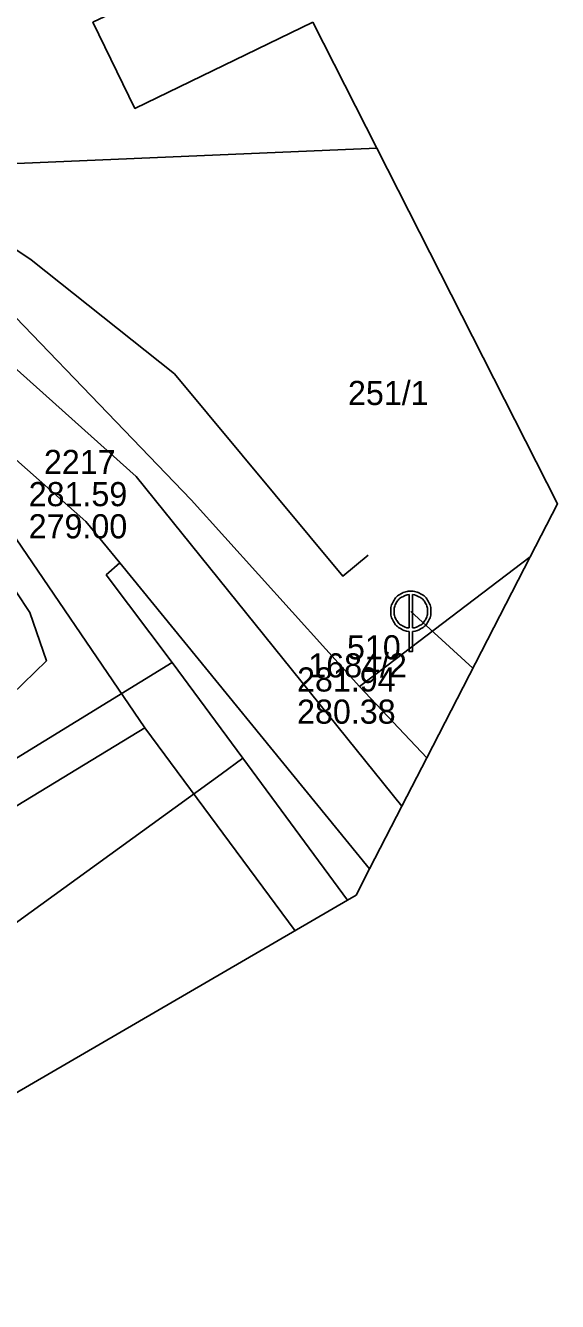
# Model space of a CAD drawing. Extents: x -571312 to -571060, y -1087128 to -1086933.
# Drawn here: x -571093.3 to -571060.1, y -1087060.8 to -1086981.5 of the extents above; entities that cross this region are included whole.
import ezdxf

# ---------------------------------------------------------------- set-up
doc = ezdxf.new("R2010")
doc.units = 0
for name, color, linetype in [('Default', 7, 'Continuous'), ('Elektro NN - vedení', 7, 'Continuous'), ('Kanalizační stoka', 7, 'Continuous'), ('Kanalizační šachta', 7, 'Continuous'), ('Parcela-polygon', 7, 'Continuous'), ('Parcela-text', 7, 'Continuous'), ('Popis šachty', 7, 'Continuous')]:
    doc.layers.add(name, color=color, linetype=linetype)

msp = doc.modelspace()

# ---------------------------------------------------------------- linework, layer by layer
at = {"layer": 'Default'}
for points in [[(-571069.383, -1087019.138), (-571069.641, -1087019.12), (-571069.903, -1087018.974), (-571070.2, -1087018.81), (-571070.365, -1087018.513), (-571070.53, -1087018.215), (-571070.53, -1087017.89), (-571070.53, -1087017.563), (-571070.362, -1087017.263), (-571070.193, -1087016.962), (-571069.895, -1087016.801), (-571069.597, -1087016.64), (-571069.28, -1087016.64), (-571068.965, -1087016.64), (-571068.666, -1087016.801), (-571068.367, -1087016.962), (-571068.198, -1087017.263), (-571068.03, -1087017.563), (-571068.03, -1087017.89), (-571068.03, -1087018.215), (-571068.195, -1087018.513), (-571068.36, -1087018.81), (-571068.657, -1087018.974), (-571068.919, -1087019.12), (-571069.177, -1087019.138)], [(-571069.383, -1087016.852), (-571069.58, -1087016.869), (-571069.795, -1087016.984), (-571070.044, -1087017.119), (-571070.183, -1087017.369), (-571070.322, -1087017.619), (-571070.322, -1087017.89), (-571070.322, -1087018.161), (-571070.186, -1087018.408), (-571070.049, -1087018.654), (-571069.8, -1087018.791), (-571069.588, -1087018.911), (-571069.383, -1087018.925)], [(-571069.177, -1087018.925), (-571068.972, -1087018.911), (-571068.758, -1087018.791), (-571068.511, -1087018.654), (-571068.374, -1087018.408), (-571068.238, -1087018.161), (-571068.238, -1087017.89), (-571068.238, -1087017.619), (-571068.378, -1087017.369), (-571068.518, -1087017.119), (-571068.767, -1087016.984), (-571068.98, -1087016.869), (-571069.177, -1087016.852)]]:
    msp.add_open_spline(points, degree=3, dxfattribs=at)
at = {"layer": 'Elektro NN - vedení'}
msp.add_lwpolyline([(-571071.926, -1087014.396), (-571073.5, -1087015.707), (-571083.992, -1087003.116), (-571092.911, -1086996.034), (-571095.272, -1086994.46), (-571113.896, -1086998.657), (-571175.538, -1087035.118), (-571177.374, -1087030.659), (-571213.311, -1086976.361), (-571216.983, -1086969.541), (-571228.263, -1086944.884), (-571229.263, -1086941.883)], dxfattribs=at)
at = {"layer": 'Kanalizační stoka'}
for points in [[(-571094.81, -1087011.96), (-571085.827, -1087025.142)], [(-571069.28, -1087017.89), (-571065.412, -1087021.418)], [(-571123.22, -1087047.86), (-571104.524, -1087036.501), (-571085.827, -1087025.142)], [(-571085.827, -1087025.142), (-571076.477, -1087037.747)]]:
    msp.add_lwpolyline(points, dxfattribs=at)
at = {"layer": 'Kanalizační šachta'}
for points in [[(-571069.383, -1087018.925), (-571069.383, -1087016.852)], [(-571069.177, -1087016.852), (-571069.177, -1087018.925)], [(-571069.177, -1087019.138), (-571069.177, -1087020.39), (-571069.383, -1087020.39), (-571069.383, -1087019.138)]]:
    msp.add_lwpolyline(points, dxfattribs=at)
at = {"layer": 'Parcela-polygon'}
for p, q in [((-571071.391, -1086989.088), (-571075.377, -1086981.251)), ((-571068.289, -1087027.004), (-571061.853, -1087014.506)), ((-571069.833, -1087030.003), (-571068.289, -1087027.004)), ((-571071.845, -1087033.911), (-571069.833, -1087030.003)), ((-571100.979, -1087051.983), (-571073.23, -1087035.86))]:
    msp.add_line(p, q, dxfattribs=at)
for points in [[(-571095.268, -1086942.132), (-571099.58, -1086936.57), (-571102.09, -1086938.18), (-571111.4, -1086944.73), (-571095.29, -1086963.14), (-571093.62, -1086968.75), (-571094.58, -1086969.01), (-571094.04, -1086970.97), (-571095.08, -1086971.25), (-571094.86, -1086972.05), (-571095.79, -1086972.31), (-571095.15, -1086974.62), (-571094.93, -1086975.43), (-571109.82, -1086979.67), (-571113.46, -1086981.09), (-571112.01, -1086983.83), (-571109.12, -1086986.12), (-571105.91, -1086988), (-571101.62, -1086990.38), (-571071.391, -1086989.088)], [(-571075.377, -1086981.251), (-571086.45, -1086986.62), (-571089.06, -1086981.26), (-571085.46, -1086979.53), (-571086.37, -1086977.73), (-571083.64, -1086976.38), (-571085.38, -1086972.81), (-571080.801, -1086970.583)], [(-571080.801, -1086970.583), (-571085.38, -1086972.81), (-571083.64, -1086976.38), (-571086.37, -1086977.73), (-571085.46, -1086979.53), (-571089.06, -1086981.26), (-571086.45, -1086986.62), (-571075.377, -1086981.251)], [(-571069.833, -1087030.003), (-571086.38, -1087009.5), (-571101.6, -1086995.89), (-571109.12, -1086986.12), (-571110.31, -1086993.17), (-571106.96, -1086996.89), (-571089.5, -1087012.31), (-571087.4, -1087014.88), (-571071.845, -1087033.911)], [(-571068.289, -1087027.004), (-571072.47, -1087022.57), (-571082.95, -1087010.95), (-571099.09, -1086994.21), (-571097.3, -1086992.63), (-571101.62, -1086990.38), (-571105.91, -1086988), (-571109.12, -1086986.12), (-571101.6, -1086995.89), (-571086.38, -1087009.5), (-571069.833, -1087030.003)], [(-571071.391, -1086989.088), (-571101.62, -1086990.38), (-571097.3, -1086992.63), (-571099.09, -1086994.21), (-571082.95, -1087010.95), (-571072.47, -1087022.57), (-571070.77, -1087021.28), (-571061.853, -1087014.506)], [(-571061.853, -1087014.506), (-571060.149, -1087011.197), (-571071.391, -1086989.088)], [(-571238.048, -1087115.573), (-571084.13, -1087021.07), (-571088.23, -1087015.62), (-571087.4, -1087014.88), (-571089.5, -1087012.31), (-571106.96, -1086996.89), (-571110.31, -1086993.17), (-571111.37, -1086999.41), (-571102.11, -1087007.86), (-571094.7, -1087015.4), (-571092.99, -1087017.97), (-571091.96, -1087020.97), (-571094.14, -1087023.09), (-571099.22, -1087026.2), (-571108.52, -1087031.9), (-571118.39, -1087037.91), (-571122.75, -1087040.66), (-571126.3, -1087042.9), (-571130.43, -1087045.33), (-571135.47, -1087048.29), (-571143.89, -1087053.63), (-571152.72, -1087058.97), (-571161.7, -1087064.52)], [(-571071.845, -1087033.911), (-571087.4, -1087014.88), (-571088.23, -1087015.62), (-571084.13, -1087021.07), (-571079.74, -1087027.03), (-571073.23, -1087035.86)], [(-571061.853, -1087014.506), (-571070.77, -1087021.28), (-571072.47, -1087022.57), (-571068.289, -1087027.004)], [(-571100.979, -1087051.983), (-571102.73, -1087043.67), (-571081.09, -1087028.01), (-571079.74, -1087027.03), (-571084.13, -1087021.07), (-571238.048, -1087115.573)], [(-571073.23, -1087035.86), (-571079.74, -1087027.03), (-571081.09, -1087028.01), (-571102.73, -1087043.67), (-571100.979, -1087051.983)], [(-571073.23, -1087035.86), (-571072.686, -1087035.544), (-571071.845, -1087033.911)]]:
    msp.add_lwpolyline(points, dxfattribs=at)
msp.add_lwpolyline([(-571091.96, -1087020.97), (-571092.99, -1087017.97), (-571094.7, -1087015.4), (-571102.11, -1087007.86), (-571111.37, -1086999.41), (-571111.41, -1086999.61), (-571107.85, -1087005.68), (-571110.89, -1087007.43), (-571108.56, -1087011.17), (-571106.51, -1087014.48), (-571099.22, -1087026.2), (-571094.14, -1087023.09)], close=True, dxfattribs=at)

# ---------------------------------------------------------------- texts
at = {"layer": 'Parcela-text'}
for s, p in [('251/1', (-571073.19, -1087005.06)), ('1684/2', (-571075.66, -1087022))]:
    msp.add_text(s, height=1.5, dxfattribs=at).set_placement(p)
at = {"layer": 'Popis šachty'}
for s, p in [('2217', (-571092.114, -1087009.351)), ('281.59', (-571093.063, -1087011.351)), ('279.00', (-571093.063, -1087013.351)), ('510', (-571073.252, -1087020.876)), ('281.94', (-571076.359, -1087022.876)), ('280.38', (-571076.359, -1087024.876))]:
    msp.add_text(s, height=1.5, dxfattribs=at).set_placement(p)

doc.saveas('drawing.dxf')
